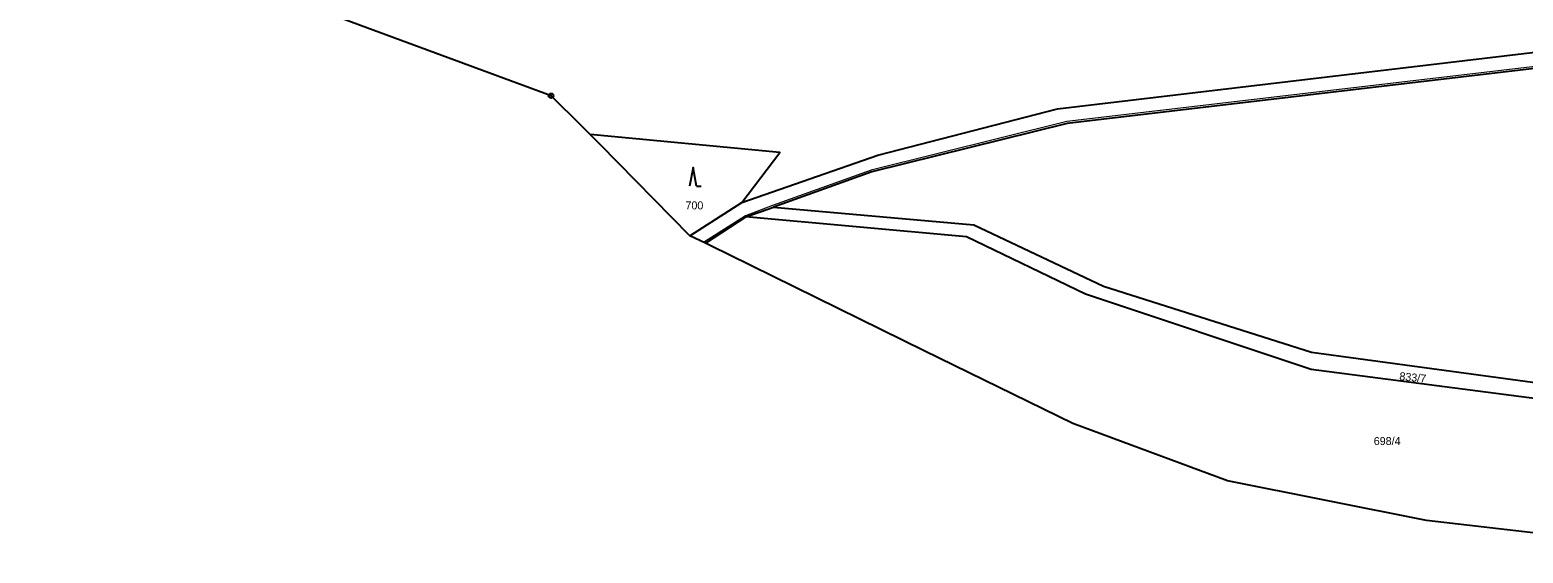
# Model space of a CAD drawing. Extents: x -687135 to -684370, y -1007309 to -1005782.
# Drawn here: x -686494.8 to -686177.6, y -1006880.7 to -1006769.6 of the extents above; entities that cross this region are included whole.
import ezdxf

# ---------------------------------------------------------------- set-up
doc = ezdxf.new("R2010")
doc.units = 0
doc.header["$LTSCALE"] = 0.68
for name, color, linetype, lineweight in [('1', 7, 'Continuous', 25), ('3', 7, 'Continuous', 25), ('4', 7, 'Continuous', 13), ('8', 7, 'Continuous', 25)]:
    doc.layers.add(name, color=color, linetype=linetype, lineweight=lineweight)
doc.layers.add('2', color=7, linetype='Continuous')

msp = doc.modelspace()

# ---------------------------------------------------------------- linework, layer by layer
at = {"layer": '1'}
for p, q in [((-686375.8, -1006791.83), (-686377.61, -1006790.04)), ((-686373.72, -1006793.93), (-686375.8, -1006791.83)), ((-686354.61, -1006813.29), (-686343.59, -1006806.28))]:
    msp.add_line(p, q, dxfattribs=at)
for points in [[(-686377.61, -1006790.04), (-686384.13, -1006783.59), (-686494.84, -1006742.74)], [(-686343.59, -1006806.28), (-686314.7, -1006796.2), (-686276.55, -1006786.38), (-686120.2, -1006767.85), (-686044, -1006772.76), (-685931.45, -1006773.3), (-685897.9, -1006785.97), (-685807.25, -1006786.78), (-685789.93, -1006767.93)], [(-686021.13, -1006775.54), (-686058.53, -1006774.98), (-686119.92, -1006771.31), (-686274.47, -1006789.46), (-686315.96, -1006799.76), (-686336.89, -1006807.26)], [(-686343.59, -1006806.28), (-686335.52, -1006795.61), (-686375.8, -1006791.83)], [(-686138.15, -1006880.65), (-686198.14, -1006873.75), (-686240.45, -1006865.3), (-686273.26, -1006853.12), (-686304.83, -1006837.74), (-686346.13, -1006817.45), (-686350.01, -1006815.54), (-686351.3, -1006814.91), (-686354.61, -1006813.29), (-686373.72, -1006793.93)], [(-686351.3, -1006814.91), (-686342.75, -1006809.32), (-686336.89, -1006807.26)], [(-686095.17, -1006868.55), (-686128.41, -1006853.95), (-686222.64, -1006841.68), (-686270.59, -1006825.7), (-686295.89, -1006813.52), (-686342.75, -1006809.32)], [(-686336.89, -1006807.26), (-686294.33, -1006810.97), (-686266.73, -1006823.99), (-686222.56, -1006838.01), (-686127.59, -1006850.89)]]:
    msp.add_lwpolyline(points, dxfattribs=at)
at = {"layer": '3'}
msp.add_line((-686353.21, -1006802.81), (-686352.214, -1006802.81), dxfattribs=at)
msp.add_lwpolyline([(-686353.21, -1006802.81), (-686353.96, -1006798.81), (-686354.71, -1006802.81)], dxfattribs=at)
at = {"layer": '4'}
msp.add_lwpolyline([(-686156.35, -1006775.23), (-686274.54, -1006789.06), (-686316.13, -1006799.39), (-686337.06, -1006806.91), (-686342.83, -1006809.05), (-686351.55, -1006814.56)], dxfattribs=at)
at = {"layer": '8'}
for radius in [0.5, 0.0303]:
    msp.add_circle((-686384.13, -1006783.5899), radius, dxfattribs=at)

# ---------------------------------------------------------------- texts
at = {"layer": '2'}
for s, p in [('700', (-686355.57, -1006807.71)), ('698/4', (-686209.35, -1006857.72))]:
    msp.add_text(s, height=1.7, dxfattribs=at).set_placement(p)
msp.add_text('833/7', height=1.7, rotation=354, dxfattribs=at).set_placement((-686203.978, -1006843.915))

doc.saveas('drawing.dxf')
